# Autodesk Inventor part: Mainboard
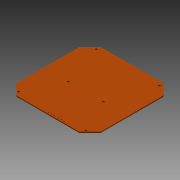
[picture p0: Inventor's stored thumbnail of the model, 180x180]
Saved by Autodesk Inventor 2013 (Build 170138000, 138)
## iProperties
Created: 2012-08
Part Number: Mainboard
Material: Phenolharz
Document SubType Name: Modeling
Designer: rYan
Mass: 30.6845 g
Surface Area: 286.415 cm^2
Volume: 22.2352 cm^3
Density: 1.38 g/cm^3
Author: rYan
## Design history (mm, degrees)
sketch "Skizze1"
  geometry: L1 (-45, -60)-(45, -60); L2 (45, -60)-(60, -45); L3 (60, -45)-(60, 45); L4 (60, 45)-(45, 60); L5 (-45, 60)-(-60, 45); L6 (-60, 45)-(-60, -45); L7 (-60, -45)-(-45, -60); L8 (0, 84)-(0, -84) reference; L9 (-84, 0)-(84, 0) reference; L10 (45, 60)-(-45, 60); 1 further point
  constraints: 16 end point, 2 parallel, 2 perpendicular, 1 horizontal, 5 other
  dimensions: "d0" = 90 distance of L1.start L1.end; "d2" = 90 distance of L2.end L3.end; "d8" = 120 distance between parallel lines of L1 L10; "d10" = 120 distance between parallel lines of L3 L6
extrude "Extrusion1" new body sketch "Skizze1" distance "d11" = 1.6; taper "d12" = 0 deg
sketch "Skizze2"
  geometry: L1 (-60, 45)-(-60, -45) reference; L2 (-45, -60)-(45, -60) reference; L3 (60, -45)-(60, 45) reference; 5 further points
  dimensions: "d13" = 12 distance from line of point (-48, -54) L1; "d28" = 6 distance from line of L2 point (-48, -54); "d29" = 6 distance from line of point (48, -54) L2; "d30" = 12 distance from line of L3 point (48, -54); "d31" = 15 distance from line of point (-45, 54) L1; "d33" = 114 distance from line of L2 point (-45, 54); "d34" = 15 distance from line of L3 point (45, 54); "d35" = 114 distance from line of L2 point (45, 54)
hole "Bohrung1" sketch "Skizze2" at (-48, -54), (-45, 54), (48, -54), (45, 54) diameter "d15" = 3; stored, may be unused: countersink angle "d19" = 90 deg, drill point angle "d21" = 118 deg; dims "d16" = 6, "d17" = 4, "d18" = 2, "d20" = 8
sketch "Skizze3"
  geometry: L1 (-45, -60)-(45, -60) reference; L2 (-60, 45)-(-60, -45) reference; L3 (21, -58)-(-7, -58); 6 further points
  constraints: 4 point on line, 2 end point, 1 midpoint, 1 perpendicular
  dimensions: "d36" = 81 distance from line of L2 L3.start; "d38" = 4 distance of L3.start point (17, -58); "d39" = 4 distance of point (13, -58) point (17, -58); "d40" = 2 distance between parallel lines of L1 L3; "d41" = 6 distance of point (13, -58) point (7, -58); "d42" = 4 distance of point (7, -58) point (3, -58); "d43" = 4 distance of point (3, -58) point (-1, -58)
hole "Bohrung2" sketch "Skizze3" at (21, -58), (17, -58), (13, -58), (7, -58), (3, -58), (-1, -58) diameter "d44" = 1.5; stored, may be unused: countersink angle "d48" = 90 deg, drill point angle "d50" = 118 deg; dims "d45" = 6, "d46" = 4, "d47" = 2, "d49" = 8
sketch "Skizze4"
  geometry: L1 (-45, -60)-(45, -60) reference; L2 (-60, 45)-(-60, -45) reference; 3 further points
  dimensions: "d51" = 85 distance from line of point (25, -6) L2; "d52" = 54 distance from line of L1 point (25, -6); "d53" = 35 distance from line of L2 point (-25, -6); "d54" = 54 distance from line of L1 point (-25, -6)
hole "Bohrung3" sketch "Skizze4" at (25, -6), (-25, -6) diameter "d55" = 3; stored, may be unused: countersink angle "d59" = 90 deg, drill point angle "d61" = 118 deg; dims "d56" = 6, "d57" = 4, "d58" = 2, "d60" = 8
node "Volumenkörper1"
